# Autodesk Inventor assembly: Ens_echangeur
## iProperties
Shininess: 64.0
Length Units: 11269
Angle Units: 11279
Time Units: 11290
Mass Units: 11283
Length Display Precision: 3
Angle Display Precision: 2
Compacted: True
Created: 2008-03
Part Number: Ens_echangeur
Document SubType Name: Assembly
Designer: Pascal
Density: 0.0
Volumn: 0.0
Area: 0.0
PropertySet Name: Model Information
Control State: 0
Master: False
Checked Out: False
Author: Pascal
